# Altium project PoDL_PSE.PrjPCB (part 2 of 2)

## Sheet 03-LAN_3-Ports_Switch.SchDoc: LAN 3-Ports Switch
size A2; Date: Thu 9th Mar, 2023; CompanyName: RGT Supply and Service Ltd.; Engineer: Nattawut; Address1: 285/95 M.3 T.Tonpao Sankampaeng; Address2: Chiangmai 50130 Thailand Tel.+66 89 1645339; Revision: 1.6; SheetNumber: 3; SheetTotal: 4; ContentRev1: Original Document; dateREV1: 09-03-2023; NameRev1: Nattawut; NameRev3: Nattawut; NameRev2: Nattawut; NameRev4: Nattawut; NameRev5: Nattawut; NameRev6: Nattawut; dateREV2: 10-05-2023; dateREV3: 29-10-2023; dateREV4: 13-12-2023; dateREV5: 14-05-2024; dateREV6: 04-07-2024; ContentRev2: Change to AD controller; ContentRev3: Update Power Coupling; ContentRev4: Correct for IC4 unused ports; ContentRev5: Improve for EMC ability; ContentRev6: Add D36, Replace FB7 to R162; Rev1: 1.0; Rev2: 1.1; Rev3: 1.2; Rev4: 1.3; Rev5: 1.4; Rev6: 1.5; Project: PoDL; PageSetup: Record=PageOptions¦CenterHorizontal=True¦CenterVertical=True¦PrintScale=0.73¦XCorrection=1.00¦YCorrection=1.00¦PrintKind=0¦BorderSize=5000000¦LeftOffset=0¦BottomOffset=0¦Orientation=2¦PaperLength=1000¦PaperWidth=1000¦Scale=100¦PaperSource=7¦PrintQuality=-3¦MediaType=1¦DitherType=10¦PrintScaleMode=1¦PaperKind=A3¦PaperIndex=8; Rev7: 1.6; ContentRev7: Improve for EMC ability; dateREV7: 15-09-2024; NameRev7: Nattawut
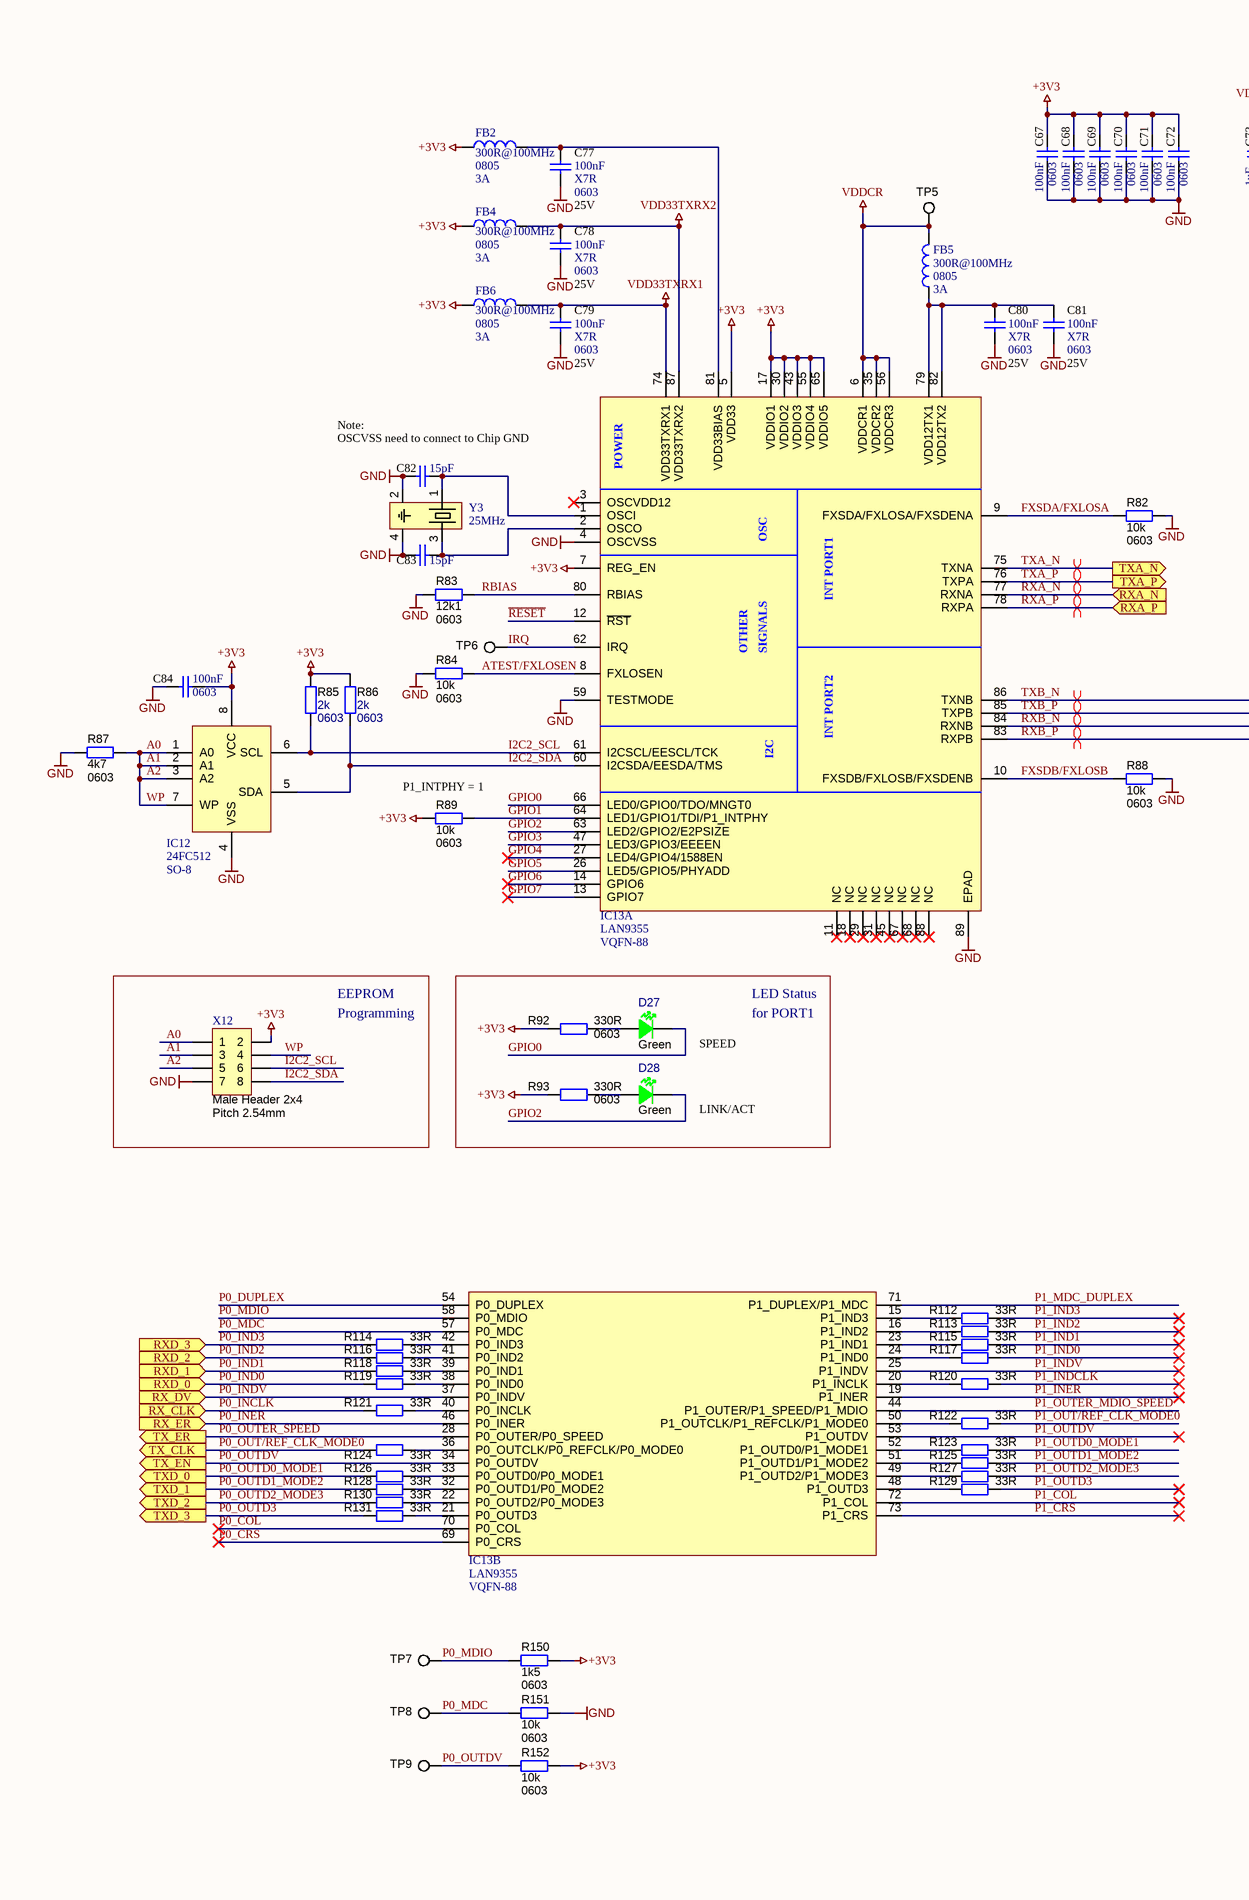
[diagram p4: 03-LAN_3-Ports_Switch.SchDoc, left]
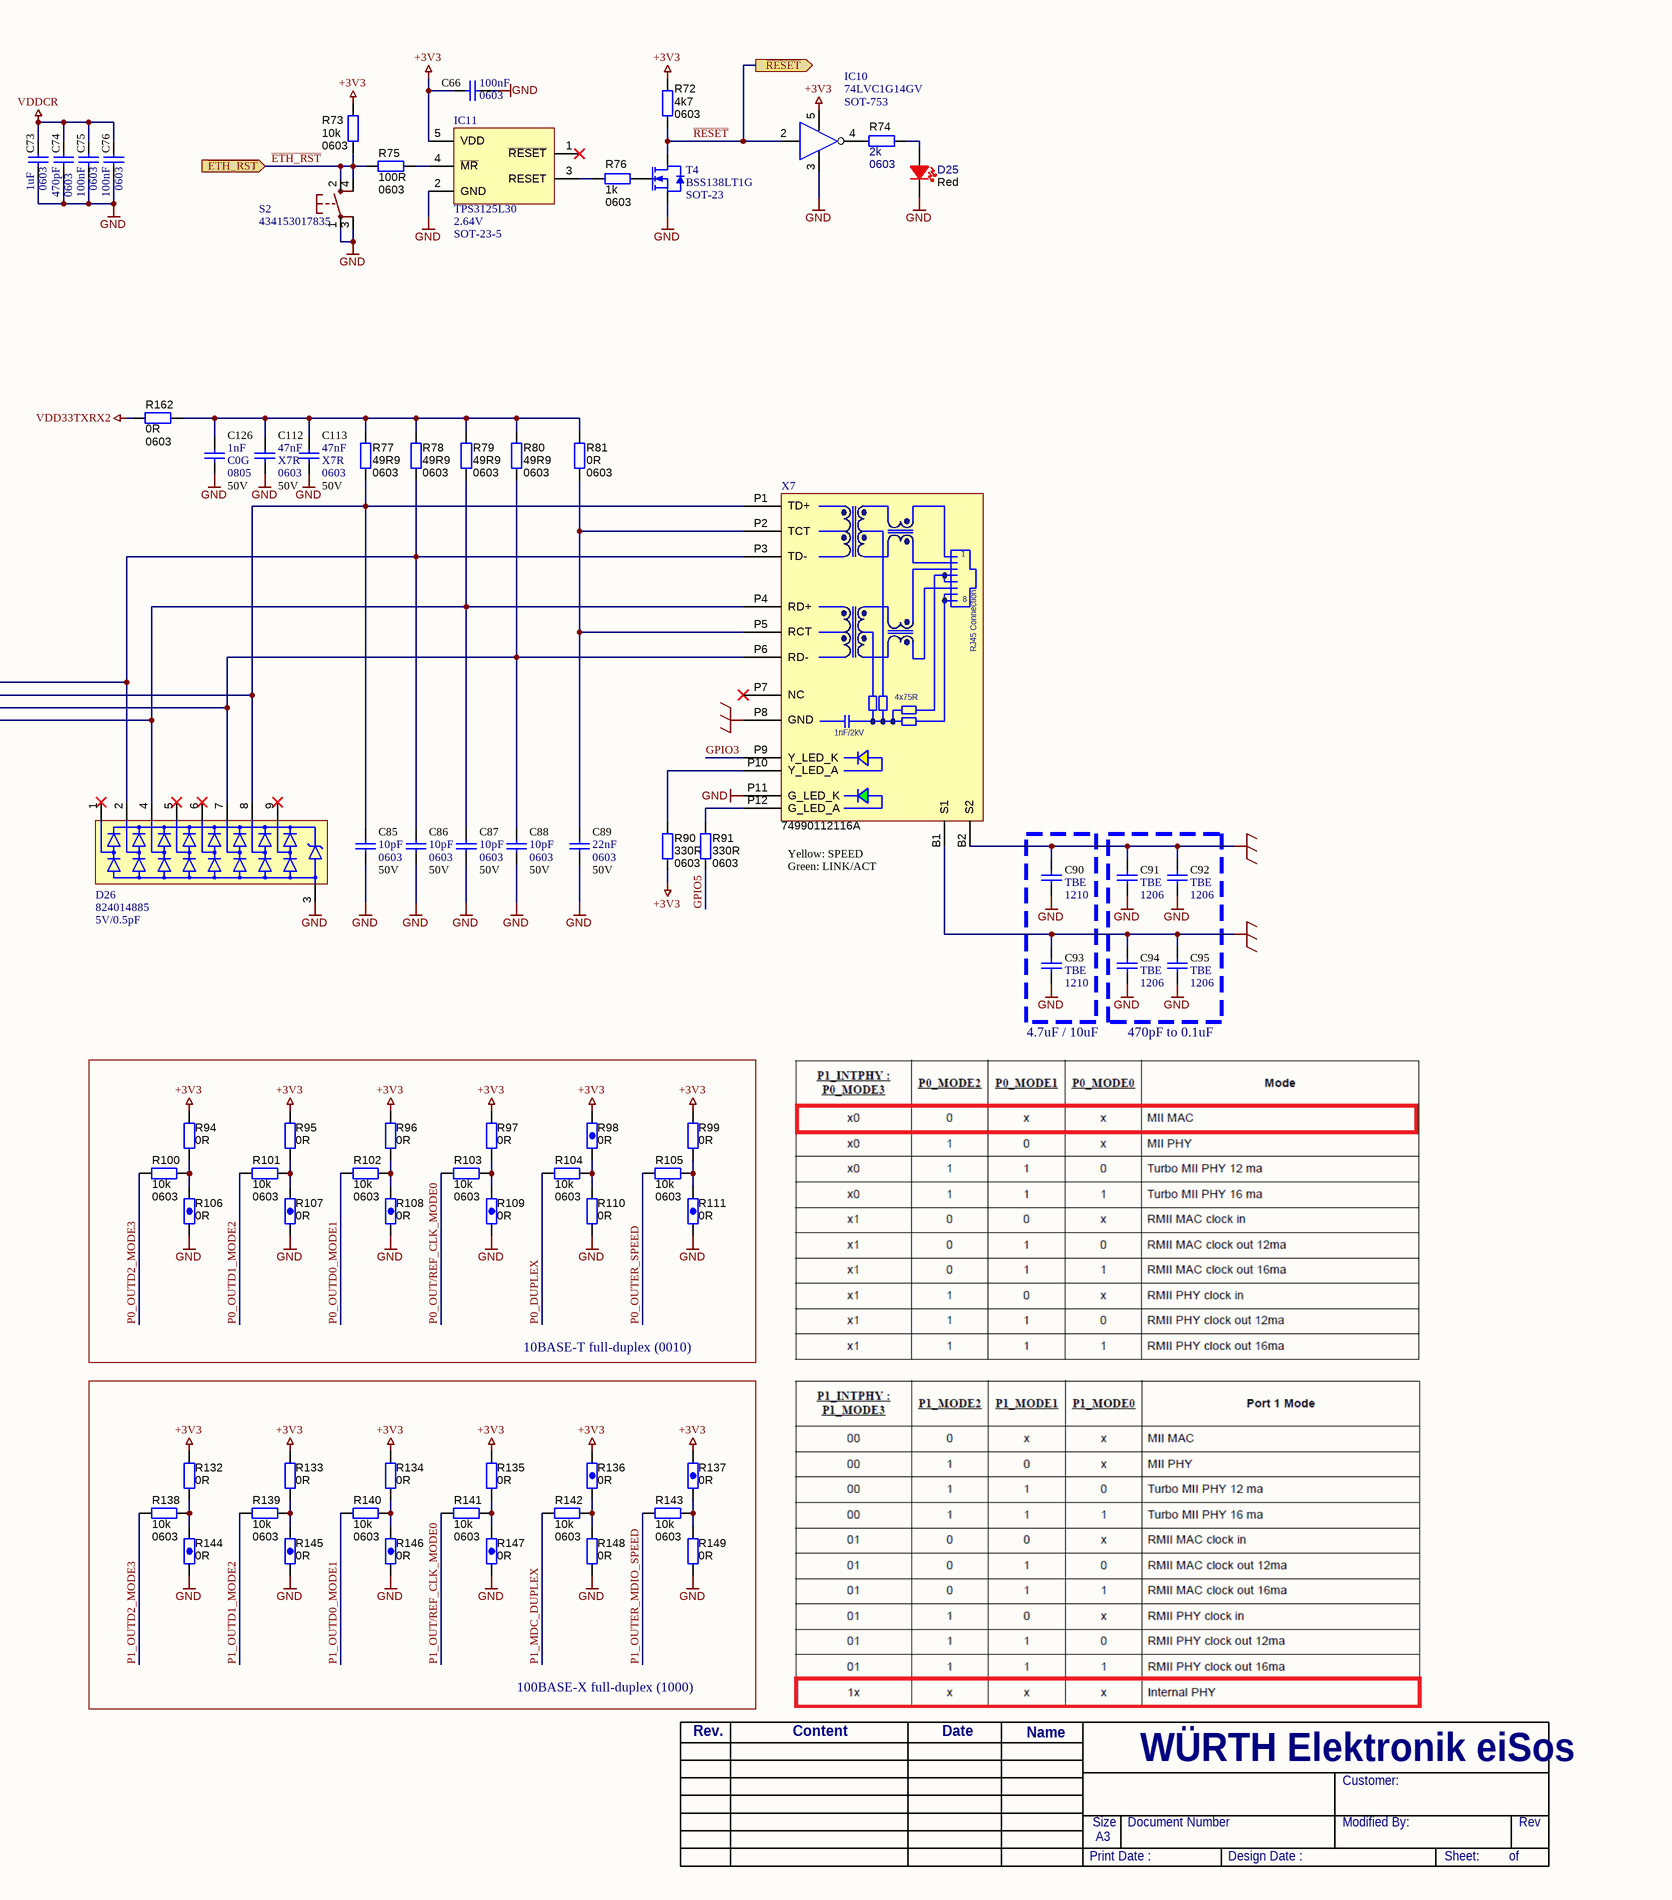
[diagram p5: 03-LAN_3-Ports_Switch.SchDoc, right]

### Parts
C66  value 100nF  PackageReference: 0603  [CC1608-0603]  (hidden comment: 885012206071)
C67  value 100nF  PackageReference: 0603  [CC1608-0603]  (hidden comment: 885012206071)
C68  value 100nF  PackageReference: 0603  [CC1608-0603]  (hidden comment: 885012206071)
C69  value 100nF  PackageReference: 0603  [CC1608-0603]  (hidden comment: 885012206071)
C70  value 100nF  PackageReference: 0603  [CC1608-0603]  (hidden comment: 885012206071)
C71  value 100nF  PackageReference: 0603  [CC1608-0603]  (hidden comment: 885012206071)
C72  value 100nF  PackageReference: 0603  [CC1608-0603]  (hidden comment: 885012206071)
C73  value 1uF  PackageReference: 0603  [CC1608-0603]  (hidden comment: 885012206026)
C74  value 470pF  PackageReference: 0603  [CC1608-0603]  (hidden comment: 885012206081)
C75  value 100nF  PackageReference: 0603  [CC1608-0603]  (hidden comment: 885012206071)
C76  value 100nF  PackageReference: 0603  [CC1608-0603]  (hidden comment: 885012206071)
C77  value 100nF  VDC_V: 25V  PackageReference: 0603  Dielectric: X7R  [CC1608-0603]  (hidden comment: 885012206071)
C78  value 100nF  VDC_V: 25V  PackageReference: 0603  Dielectric: X7R  [CC1608-0603]  (hidden comment: 885012206071)
C79  value 100nF  VDC_V: 25V  PackageReference: 0603  Dielectric: X7R  [CC1608-0603]  (hidden comment: 885012206071)
C80  value 100nF  VDC_V: 25V  PackageReference: 0603  Dielectric: X7R  [CC1608-0603]  (hidden comment: 885012206071)
C81  value 100nF  VDC_V: 25V  PackageReference: 0603  Dielectric: X7R  [CC1608-0603]  (hidden comment: 885012206071)
C82  value 15pF  [CC1005-0402]  (hidden comment: 885012005056)
C83  value 15pF  [CC1005-0402]  (hidden comment: 885012005056)
C84  value 100nF  PackageReference: 0603  [CC1608-0603]  (hidden comment: 885012206071)
C85  value 10pF  VDC_V: 50V  PackageReference: 0603  [CC1608-0603]  (hidden comment: 885012006051)
C86  value 10pF  VDC_V: 50V  PackageReference: 0603  [CC1608-0603]  (hidden comment: 885012006051)
C87  value 10pF  VDC_V: 50V  PackageReference: 0603  [CC1608-0603]  (hidden comment: 885012006051)
C88  value 10pF  VDC_V: 50V  PackageReference: 0603  [CC1608-0603]  (hidden comment: 885012006051)
C89  value 22nF  VDC_V: 50V  PackageReference: 0603  [CC1608-0603]  (hidden comment: 885012206091)
C90  value TBE  PackageReference: 1210  [CC3225-1210]
C91  value TBE  PackageReference: 1206  [CC3216-1206]
C92  value TBE  PackageReference: 1206  [CC3216-1206]
C93  value TBE  PackageReference: 1210  [CC3225-1210]
C94  value TBE  PackageReference: 1206  [CC3216-1206]
C95  value TBE  PackageReference: 1206  [CC3216-1206]
C112  value 47nF  VDC_V: 50V  PackageReference: 0603  Dielectric: X7R  [CC1608-0603]  (hidden comment: 885012206093)
C113  value 47nF  VDC_V: 50V  PackageReference: 0603  Dielectric: X7R  [CC1608-0603]  (hidden comment: 885012206093)
C126  value 1nF  VDC_V: 50V  PackageReference: 0805  Dielectric: C0G  [CC2012-0805]  (hidden comment: 885012007063)
D25  value Red  [LED1608 (0603) - Red]  (hidden comment: 150060SS75020)
D26  Voltage: 5V/0.5pF  [WE-TVS_824014885]  (hidden comment: 824014885)
D27  value Green  [LED1608 (0603) - Green]  (hidden comment: 150060VS75020)
D28  value Green  [LED1608 (0603) - Green]  (hidden comment: 150060VS75020)
FB2  value 300R@100MHz  PackageReference: 0805  I DC: 3A  [CF2012-0805]  (hidden comment: 742792031)
FB4  value 300R@100MHz  PackageReference: 0805  I DC: 3A  [CF2012-0805]  (hidden comment: 742792031)
FB5  value 300R@100MHz  PackageReference: 0805  I DC: 3A  [CF2012-0805]  (hidden comment: 742792031)
FB6  value 300R@100MHz  PackageReference: 0805  I DC: 3A  [CF2012-0805]  (hidden comment: 742792031)
IC10  value 74LVC1G14GV  PackageReference: SOT-753  [SOT-23-5]  (hidden comment: 74LVC1G14GV,125)
IC11  value TPS3125L30  Threshold Voltage: 2.64V  [SOT-23-5]  (hidden comment: TPS3125L30DBVR)
IC12  value 24FC512  [SO-8]  (hidden comment: 24FC512-I/SN)
IC13  value LAN9355  PackageReference: VQFN-88  [QFN-88 12X12MM]  (hidden comment: LAN9355I/ML)  (parts A,B of 2)
R72  value 4k7  PackageReference: 0603  [CR1608-0603]  (hidden comment: 560112116006)
R73  value 10k  PackageReference: 0603  [CR1608-0603]  (hidden comment: 560112116005)
R74  value 2k  PackageReference: 0603  [CR1608-0603]  (hidden comment: 560112116091)
R75  value 100R  PackageReference: 0603  [CR1608-0603]  (hidden comment: 560112116009)
R76  value 1k  PackageReference: 0603  [CR1608-0603]  (hidden comment: 560112116014)
R77  value 49R9  PackageReference: 0603  [CR1608-0603]  (hidden comment: 560112116133)
R78  value 49R9  PackageReference: 0603  [CR1608-0603]  (hidden comment: 560112116133)
R79  value 49R9  PackageReference: 0603  [CR1608-0603]  (hidden comment: 560112116133)
R80  value 49R9  PackageReference: 0603  [CR1608-0603]  (hidden comment: 560112116133)
R81  value 0R  PackageReference: 0603  [CR1608-0603]  (hidden comment: RC0603FR-070RL)
R82  value 10k  PackageReference: 0603  [CR1608-0603]  (hidden comment: 560112116005)
R83  value 12k1  PackageReference: 0603  [CR1608-0603]  (hidden comment: RC0603FR-0712K1L)
R84  value 10k  PackageReference: 0603  [CR1608-0603]  (hidden comment: 560112116005)
R85  value 2k  PackageReference: 0603  [CR1608-0603]  (hidden comment: 560112116091)
R86  value 2k  PackageReference: 0603  [CR1608-0603]  (hidden comment: 560112116091)
R87  value 4k7  PackageReference: 0603  [CR1608-0603]  (hidden comment: 560112116006)
R88  value 10k  PackageReference: 0603  [CR1608-0603]  (hidden comment: 560112116005)
R89  value 10k  PackageReference: 0603  [CR1608-0603]  (hidden comment: 560112116005)
R90  value 330R  PackageReference: 0603  [CR1608-0603]  (hidden comment: 560112116020)
R91  value 330R  PackageReference: 0603  [CR1608-0603]  (hidden comment: 560112116020)
R92  value 330R  PackageReference: 0603  [CR1608-0603]  (hidden comment: 560112116020)
R93  value 330R  PackageReference: 0603  [CR1608-0603]  (hidden comment: 560112116020)
R94  value 0R  [CR1608-0603]  (hidden comment: RC0603FR-070RL)
R95  value 0R  [CR1608-0603]  (hidden comment: RC0603FR-070RL)
R96  value 0R  [CR1608-0603]  (hidden comment: RC0603FR-070RL)
R97  value 0R  [CR1608-0603]  (hidden comment: RC0603FR-070RL)
R98  value 0R  [CR1608-0603]  (hidden comment: RC0603FR-070RL)
R99  value 0R  [CR1608-0603]  (hidden comment: RC0603FR-070RL)
R100  value 10k  PackageReference: 0603  [CR1608-0603]  (hidden comment: 560112116005)
R101  value 10k  PackageReference: 0603  [CR1608-0603]  (hidden comment: 560112116005)
R102  value 10k  PackageReference: 0603  [CR1608-0603]  (hidden comment: 560112116005)
R103  value 10k  PackageReference: 0603  [CR1608-0603]  (hidden comment: 560112116005)
R104  value 10k  PackageReference: 0603  [CR1608-0603]  (hidden comment: 560112116005)
R105  value 10k  PackageReference: 0603  [CR1608-0603]  (hidden comment: 560112116005)
R106  value 0R  [CR1608-0603]  (hidden comment: RC0603FR-070RL)
R107  value 0R  [CR1608-0603]  (hidden comment: RC0603FR-070RL)
R108  value 0R  [CR1608-0603]  (hidden comment: RC0603FR-070RL)
R109  value 0R  [CR1608-0603]  (hidden comment: RC0603FR-070RL)
R110  value 0R  [CR1608-0603]  (hidden comment: RC0603FR-070RL)
R111  value 0R  [CR1608-0603]  (hidden comment: RC0603FR-070RL)
R112  value 33R  [CR1608-0603]  (hidden comment: 560112116034)
R113  value 33R  [CR1608-0603]  (hidden comment: 560112116034)
R114  value 33R  [CR1608-0603]  (hidden comment: 560112116034)
R115  value 33R  [CR1608-0603]  (hidden comment: 560112116034)
R116  value 33R  [CR1608-0603]  (hidden comment: 560112116034)
R117  value 33R  [CR1608-0603]  (hidden comment: 560112116034)
R118  value 33R  [CR1608-0603]  (hidden comment: 560112116034)
R119  value 33R  [CR1608-0603]  (hidden comment: 560112116034)
R120  value 33R  [CR1608-0603]  (hidden comment: 560112116034)
R121  value 33R  [CR1608-0603]  (hidden comment: 560112116034)
R122  value 33R  [CR1608-0603]  (hidden comment: 560112116034)
R123  value 33R  [CR1608-0603]  (hidden comment: 560112116034)
R124  value 33R  [CR1608-0603]  (hidden comment: 560112116034)
R125  value 33R  [CR1608-0603]  (hidden comment: 560112116034)
R126  value 33R  [CR1608-0603]  (hidden comment: 560112116034)
R127  value 33R  [CR1608-0603]  (hidden comment: 560112116034)
R128  value 33R  [CR1608-0603]  (hidden comment: 560112116034)
R129  value 33R  [CR1608-0603]  (hidden comment: 560112116034)
R130  value 33R  [CR1608-0603]  (hidden comment: 560112116034)
R131  value 33R  [CR1608-0603]  (hidden comment: 560112116034)
R132  value 0R  [CR1608-0603]  (hidden comment: RC0603FR-070RL)
R133  value 0R  [CR1608-0603]  (hidden comment: RC0603FR-070RL)
R134  value 0R  [CR1608-0603]  (hidden comment: RC0603FR-070RL)
R135  value 0R  [CR1608-0603]  (hidden comment: RC0603FR-070RL)
R136  value 0R  [CR1608-0603]  (hidden comment: RC0603FR-070RL)
R137  value 0R  [CR1608-0603]  (hidden comment: RC0603FR-070RL)
R138  value 10k  PackageReference: 0603  [CR1608-0603]  (hidden comment: 560112116005)
R139  value 10k  PackageReference: 0603  [CR1608-0603]  (hidden comment: 560112116005)
R140  value 10k  PackageReference: 0603  [CR1608-0603]  (hidden comment: 560112116005)
R141  value 10k  PackageReference: 0603  [CR1608-0603]  (hidden comment: 560112116005)
R142  value 10k  PackageReference: 0603  [CR1608-0603]  (hidden comment: 560112116005)
R143  value 10k  PackageReference: 0603  [CR1608-0603]  (hidden comment: 560112116005)
R144  value 0R  [CR1608-0603]  (hidden comment: RC0603FR-070RL)
R145  value 0R  [CR1608-0603]  (hidden comment: RC0603FR-070RL)
R146  value 0R  [CR1608-0603]  (hidden comment: RC0603FR-070RL)
R147  value 0R  [CR1608-0603]  (hidden comment: RC0603FR-070RL)
R148  value 0R  [CR1608-0603]  (hidden comment: RC0603FR-070RL)
R149  value 0R  [CR1608-0603]  (hidden comment: RC0603FR-070RL)
R150  value 1k5  PackageReference: 0603  [CR1608-0603]  (hidden comment: 560112116038)
R151  value 10k  PackageReference: 0603  [CR1608-0603]  (hidden comment: 560112116005)
R152  value 10k  PackageReference: 0603  [CR1608-0603]  (hidden comment: 560112116005)
R162  value 0R  PackageReference: 0603  [CR1608-0603]  (hidden comment: RC0603FR-070RL)
S2  434153017835  [434153017835]
T4  BSS138LT1G  [SOT-23]
TP5  (no value)  [TESTPOINT 1.5mm]
TP6  (no value)  [TESTPOINT 1.5mm]
TP7  (no value)  [TESTPOINT 1.5mm]
TP8  (no value)  [TESTPOINT 1.5mm]
TP9  (no value)  [TESTPOINT 1.5mm]
X7  74990112116A  [RJ45_74990112116A]
X12  value Male Header 2x4  PackageReference: Pitch 2.54mm  [HDR2X4]  (hidden comment: 61300821121)
Y3  value 25MHz  [CRYSTAL_3225]  (hidden comment: 830055299)

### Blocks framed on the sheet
10BASE-T full-duplex (0010): R94-R111
100BASE-X full-duplex (1000): R132-R149

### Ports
RX_CLK (in), RX_DV (in), RX_ER (in), RXA_N (in), RXA_P (in), RXD_0 (in), RXD_1 (in), RXD_2 (in), RXD_3 (in), TX_CLK (out), TX_EN (out), TX_ER (out), TXA_N (out), TXA_P (out), TXD_0 (out), TXD_1 (out), TXD_2 (out), TXD_3 (out), ~{ETH_RST} (in), ~{RESET} (out)

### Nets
+3V3: C66.2 C67.1 C68.1 C69.1 C70.1 C71.1 C72.1 C84.2 FB2.1 FB4.1 FB6.1 IC10.5(Vcc) IC11.5(VDD) IC12.8(VCC) IC13.5(VDD33) IC13.7(REG_EN) IC13.17(VDDIO1) IC13.30(VDDIO2) IC13.43(VDDIO3) IC13.55(VDDIO4) IC13.65(VDDIO5) R72.1 R73.2 R85.1 R86.1 R89.1 R90.2 R92.1 R93.1 R94.2 R95.2 R96.2 R97.2 R98.2 R99.2 R132.2 R133.2 R134.2 R135.2 R136.2 R137.2 R150.2 R152.1 X12.2
GND: C66.1 C67.2 C68.2 C69.2 C70.2 C71.2 C72.2 C73.1 C74.2 C75.2 C76.2 C77.2 C78.2 C79.2 C80.2 C81.2 C82.1 C83.1 C84.1 C85.2 C86.2 C87.2 C88.2 C89.2 C90.2 C91.2 C92.2 C93.2 C94.2 C95.2 C112.2 C113.2 C126.2 D25.1 D26.3(GND) IC10.3(Gnd) IC11.2(GND) IC12.4(VSS) IC13.4(OSCVSS) IC13.59(TESTMODE) IC13.89(EPAD) R82.2 R83.2 R84.1 R87.2 R88.2 R106.1 R107.1 R108.1 R109.1 R110.1 R111.1 R144.1 R145.1 R146.1 R147.1 R148.1 R149.1 R151.1 S2.1 S2.3 T4.2(S) X7.P11(G_LED_K) X12.7 Y3.2 Y3.4
SHIELD: C90.1 C91.1 C92.1 C93.1 C94.1 C95.1 X7.B1(S1) X7.B2(S2) X7.P8(GND)
VDD33TXRX1: C79.1 FB6.2 IC13.74(VDD33TXRX1)
VDD33TXRX2: C78.1 FB4.2 IC13.87(VDD33TXRX2) R162.1
VDDCR: C73.2 C74.1 C75.1 C76.1 FB5.2 IC13.6(VDDCR1) IC13.35(VDDCR2) IC13.56(VDDCR3) TP5.1
A0: IC12.1(A0) IC12.2(A1) IC12.3(A2) IC12.7(WP) R87.1 X12.1 X12.3 X12.4 X12.5  [also labelled A1, A2, WP]
ATEST/FXLOSEN: IC13.8(FXLOSEN) R84.2
~{ETH_RST}: R73.1 R75.1 S2.2 S2.4 ; port ~{ETH_RST}
FXSDA/FXLOSA: IC13.9(FXSDA/FXLOSA/FXSDENA) R82.1
FXSDB/FXLOSB: IC13.10(FXSDB/FXLOSB/FXSDENB) R88.1
GPIO0: D27.1 IC13.66(LED0/GPIO0/TDO/MNGT0)
GPIO1: IC13.64(LED1/GPIO1/TDI/P1_INTPHY) R89.2
GPIO2: D28.1 IC13.63(LED2/GPIO2/E2PSIZE)
GPIO3: IC13.47(LED3/GPIO3/EEEEN) X7.P9(Y_LED_K)
GPIO4: IC13.27(LED4/GPIO4/1588EN)
GPIO5: IC13.26(LED5/GPIO5/PHYADD) R91.2
GPIO6: IC13.14(GPIO6)
GPIO7: IC13.13(GPIO7)
I2C2_SCL: IC12.6(SCL) IC13.61(I2CSCL/EESCL/TCK) R85.2 X12.6
I2C2_SDA: IC12.5(SDA) IC13.60(I2CSDA/EESDA/TMS) R86.2 X12.8
IRQ: IC13.62(IRQ) TP6.1
P0_COL: IC13.70(P0_COL)
P0_CRS: IC13.69(P0_CRS)
P0_DUPLEX: IC13.54(P0_DUPLEX) R104.1
P0_INCLK: R121.1 ; port RX_CLK
P0_IND0: R119.1 ; port RXD_0
P0_IND1: R118.1 ; port RXD_1
P0_IND2: R116.1 ; port RXD_2
P0_IND3: R114.1 ; port RXD_3
P0_INDV: IC13.37(P0_INDV) ; port RX_DV
P0_INER: IC13.46(P0_INER) ; port RX_ER
P0_MDC: IC13.57(P0_MDC) R151.2 TP8.1
P0_MDIO: IC13.58(P0_MDIO) R150.1 TP7.1
P0_OUT/REF_CLK_MODE0: R103.1 R124.1 ; port TX_CLK
P0_OUTD0_MODE1: R102.1 R126.1 ; port TXD_0
P0_OUTD1_MODE2: R101.1 R128.1 ; port TXD_1
P0_OUTD2_MODE3: R100.1 R130.1 ; port TXD_2
P0_OUTD3: R131.1 ; port TXD_3
P0_OUTDV: IC13.34(P0_OUTDV) R152.2 TP9.1 ; port TX_EN
P0_OUTER_SPEED: IC13.28(P0_OUTER/P0_SPEED) R105.1 ; port TX_ER
P1_COL: IC13.72(P1_COL)
P1_CRS: IC13.73(P1_CRS)
P1_IND0: R117.2
P1_IND1: R115.2
P1_IND2: R113.2
P1_IND3: R112.2
P1_INDCLK: R120.2
P1_INDV: IC13.25(P1_INDV)
P1_INER: IC13.19(P1_INER)
P1_MDC_DUPLEX: IC13.71(P1_DUPLEX/P1_MDC) R142.1
P1_OUT/REF_CLK_MODE0: R122.2 R141.1
P1_OUTD0_MODE1: R123.2 R140.1
P1_OUTD1_MODE2: R125.2 R139.1
P1_OUTD2_MODE3: R127.2 R138.1
P1_OUTD3: R129.2
P1_OUTDV: IC13.53(P1_OUTDV)
P1_OUTER_MDIO_SPEED: IC13.44(P1_OUTER/P1_SPEED/P1_MDIO) R143.1
~{RESET}: IC10.2(A) IC13.12(~{RST}) R72.2 T4.3(D) ; port ~{RESET}
RBIAS: IC13.80(RBIAS) R83.1
RXA_N: IC13.77(RXNA) ; port RXA_N
RXA_P: IC13.78(RXPA) ; port RXA_P
RXB_N: C88.1 D26.7(IO6) IC13.84(RXNB) R80.1 X7.P6(RD-)
RXB_P: C87.1 D26.4(IO3) IC13.83(RXPB) R79.1 X7.P4(RD+)
TXA_N: IC13.75(TXNA) ; port TXA_N
TXA_P: IC13.76(TXPA) ; port TXA_P
TXB_N: C86.1 D26.2(IO2) IC13.86(TXNB) R78.1 X7.P3(TD-)
TXB_P: C85.1 D26.8(IO7) IC13.85(TXPB) R77.1 X7.P1(TD+)
NetC77_1: C77.1 FB2.2 IC13.81(VDD33BIAS)
NetC80_1: C80.1 C81.1 FB5.1 IC13.79(VDD12TX1) IC13.82(VDD12TX2)
NetC82_2: C82.2 IC13.1(OSCI) Y3.1
NetC83_2: C83.2 IC13.2(OSCO) Y3.3
NetC89_1: C89.1 R81.1 X7.P2(TCT) X7.P5(RCT)
NetC112_1: C112.1 C113.1 C126.1 R77.2 R78.2 R79.2 R80.2 R81.2 R162.2
NetD25_2: D25.2 R74.2
NetD27_2: D27.2 R92.2
NetD28_2: D28.2 R93.2
NetIC10_4: IC10.4(Y) R74.1
NetIC11_3: IC11.3(RESET) R76.1
NetIC11_4: IC11.4(~{MR}) R75.2
NetIC13_15: IC13.15(P1_IND3) R112.1
NetIC13_16: IC13.16(P1_IND2) R113.1
NetIC13_20: IC13.20(P1_INCLK) R120.1
NetIC13_21: IC13.21(P0_OUTD3) R131.2
NetIC13_22: IC13.22(P0_OUTD2/P0_MODE3) R130.2
NetIC13_23: IC13.23(P1_IND1) R115.1
NetIC13_24: IC13.24(P1_IND0) R117.1
NetIC13_32: IC13.32(P0_OUTD1/P0_MODE2) R128.2
NetIC13_33: IC13.33(P0_OUTD0/P0_MODE1) R126.2
NetIC13_36: IC13.36(P0_OUTCLK/P0_REFCLK/P0_MODE0) R124.2
NetIC13_38: IC13.38(P0_IND0) R119.2
NetIC13_39: IC13.39(P0_IND1) R118.2
NetIC13_40: IC13.40(P0_INCLK) R121.2
NetIC13_41: IC13.41(P0_IND2) R116.2
NetIC13_42: IC13.42(P0_IND3) R114.2
NetIC13_48: IC13.48(P1_OUTD3) R129.1
NetIC13_49: IC13.49(P1_OUTD2/P1_MODE3) R127.1
NetIC13_50: IC13.50(P1_OUTCLK/P1_REFCLK/P1_MODE0) R122.1
NetIC13_51: IC13.51(P1_OUTD1/P1_MODE2) R125.1
NetIC13_52: IC13.52(P1_OUTD0/P1_MODE1) R123.1
NetR76_2: R76.2 T4.1(G)
NetR90_1: R90.1 X7.P10(Y_LED_A)
NetR91_1: R91.1 X7.P12(G_LED_A)
NetR94_1: R94.1 R100.2 R106.2
NetR95_1: R95.1 R101.2 R107.2
NetR96_1: R96.1 R102.2 R108.2
NetR97_1: R97.1 R103.2 R109.2
NetR98_1: R98.1 R104.2 R110.2
NetR99_1: R99.1 R105.2 R111.2
NetR132_1: R132.1 R138.2 R144.2
NetR133_1: R133.1 R139.2 R145.2
NetR134_1: R134.1 R140.2 R146.2
NetR135_1: R135.1 R141.2 R147.2
NetR136_1: R136.1 R142.2 R148.2
NetR137_1: R137.1 R143.2 R149.2

Not connected (* = marked no-connect by the designer): D26 1(IO1)* 5(IO4)* 6(IO5)* 9(IO8)*; IC11 1(~{RESET})*; IC13 3(OSCVDD12)* 11(NC)* 18(NC)* 29(NC)* 31(NC)* 45(NC)* 67(NC)* 68(NC)* 88(NC)*; X7 P7(NC)*

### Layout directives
differential pair: RXA_N, RXA_P, RXB_N, RXB_P, TXA_N, TXA_P, TXB_N, TXB_P

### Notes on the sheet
- (near C82) Note:
  OSCVSS need to connect to Chip GND
- (near R89) P1_INTPHY = 1
- (near X7) Yellow: SPEED
  Green: LINK/ACT
- EEPROM
- LED Status
- Programming
- SPEED
- for PORT1
- 4.7uF / 10uF
- 470pF to 0.1uF
- (near D28) LINK/ACT
- Rev.
- Content
- Date
- Name
- WÜRTH Elektronik eiSos
- Customer:
- Print Date :
- Size
- A3
- Document Number
- Design Date :
- Modified By:
- Sheet:
- of
- Rev

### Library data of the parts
C66-C72 C75-C81 C84 = 885012206071: CAP, CERM, 100nF, 25V, +/-10%, X7R, 0603; Manufacturer: Wurth; Polarized: N; TaMax_C: 125; TaMin_C: -55; Tolerance_%: 10; CompType: Capacitor
C73 = 885012206026: CAP, CERM, 1uF, 10V, +/-10%, X7R, 0603; Manufacturer: Wurth; Polarized: N; TaMax_C: 125; TaMin_C: -55; Tolerance_%: 10%; CompType: Capacitor
C74 = 885012206081: CAP, CERM, 470pF, 50V, +/-10%, X7R, 0603; Manufacturer: Wurth; Polarized: N; TaMax_C: 125; TaMin_C: -55; Tolerance_%: 10; CompType: Capacitor
C82 C83 = 885012005056: CAP, CERM, 15pF, 50V, +/-5%, C0G, 0402; Manufacturer: Wurth; Polarized: N; TaMax_C: 125; TaMin_C: -55; Tolerance_%: 5; CompType: Capacitor
C85-C88 = 885012006051: CAP, CERM, 10pF, 50V, +/-5%, C0G, 0603; Manufacturer: Wurth; Polarized: N; TaMax_C: 125; TaMin_C: -55; Tolerance_%: 5; CompType: Capacitor
C89 = 885012206091: CAP, CERM, 22nF, 50V, +/-10%, X7R, 0603; Manufacturer: Wurth; Polarized: N; TaMax_C: 125; TaMin_C: -55; Tolerance_%: 10%; CompType: Capacitor
C90 C93 = TBE_CAP_1210: CAP, CERM, TBE, 1210; Polarized: N; TaMax_C: 125; TaMin_C: -55; CompType: Capacitor
C91 C92 C94 C95 = TBE_CAP_1206: CAP, CERM, TBE, 1206; Polarized: N; TaMax_C: 125; TaMin_C: -55; CompType: Capacitor
C112 C113 = 885012206093: CAP, CERM, 47nF, 50V, +/-10%, X7R, 0603; Manufacturer: Wurth; Polarized: N; TaMax_C: 125; TaMin_C: -55; Tolerance_%: 10%; CompType: Capacitor
C126 = 885012007063: CAP, CERM, 1nF, 50V, +/-5%, C0G, 0805; Manufacturer: Wurth; Polarized: N; TaMax_C: 125; TaMin_C: -55; Tolerance_%: 5; CompType: Capacitor
D25 = 150060SS75020: LED 645NM RED 0603 SMD; Manufacturer: Wurth
D26 = 824014885: DIODE, TVS Super Speed , 5V, 8CH, 3.8x1.0mm; Manufacturer: Wurth
D27 D28 = 150060VS75020: LED 572NM GREEN 0603 SMD; Manufacturer: Wurth
FB2 FB4-FB6 = 742792031: Ferrite Bead 300R @ 100MHz / 0805 / 3.0A; Manufacturer: Wurth
IC10 = 74LVC1G14GV,125_2: IC SCHMITT INVERTER, 1.65-5.5V, 1CH, SOT-753; Manufacturer: Nexperia
IC11 = TPS3125L30DBVR: IC Supervisory, 0.75-3.3V, SOT-23-5; Manufacturer: TI
IC12 = 24FC512-I/SN: IC EEPROM, I2C, 512kb, 1MHz, 1.7-5.5V, SO-8; Manufacturer: Microchip
IC13 = LAN9355I/ML: IC ETHERNET SWITCH 3PORT, VQFN-88; Manufacturer: Microchip
R72 R87 = 560112116006: RES, 4.7kohm, 1%, 0.1W, 0603; Manufacturer: Wurth; CompType: Resistor; Power_W: 0.1
R73 R82 R84 R88 R89 R100-R105 R138-R143 R151 R152 = 560112116005: RES, 10kohm, 1%, 0.1W, 0603; Manufacturer: Wurth; CompType: Resistor; Power_W: 0.1
R74 R85 R86 = 560112116091: RES, 2kohm, 1%, 0.1W, 0603; Manufacturer: Wurth; CompType: Resistor; Power_W: 0.1
R75 = 560112116009: RES, 100 ohm, 1%, 0.1W, 0603; Manufacturer: Wurth; CompType: Resistor; Power_W: 0.1
R76 = 560112116014: RES, 1kohm, 1%, 0.1W, 0603; Manufacturer: Wurth; CompType: Resistor; Power_W: 0.1
R77-R80 = 560112116133: RES, 49.9 ohm, 1%, 0.1W, 0603; Manufacturer: Wurth; CompType: Resistor; Power_W: 0.1
R81 R94-R99 R106-R111 R132-R137 R144-R149 R162 = RC0603FR-070RL: RES, 0 ohm, 1%, 0.1W, 0603; Manufacturer: Yageo; CompType: Resistor; Power_W: 0.1
R83 = RC0603FR-0712K1L: RES, 12.1kohm, 1%, 0.1W, 0603; Manufacturer: Yageo; CompType: Resistor; Power_W: 0.1
R90-R93 = 560112116020: RES, 330 ohm, 1%, 0.1W, 0603; Manufacturer: Wurth; CompType: Resistor; Power_W: 0.1
R112-R131 = 560112116034: RES, 33 ohm, 1%, 0.1W, 0603; Manufacturer: Wurth; CompType: Resistor; Power_W: 0.1
R150 = 560112116038: RES, 1.5kohm, 1%, 0.1W, 0603; Manufacturer: Wurth; CompType: Resistor; Power_W: 0.1
S2 = 434153017835: SWITCH TACTILE, SPST-NO, 350gf, 0.05A, 12V; Manufacturer: Wurth
T4 = BSS138LT1G: MOSFET, N-CH, 50V, 0.2A, SOT-23; Manufacturer: Onsemi
TP5-TP9 = TP / 1.5mm: Test Point, SMT, Miniature; Value: 1.5mm
X7 = 74990112116A: CON, Ethernet, Int Magnetics, 8P+LED, 1x1 Tab-UP, INS; Manufacturer: Wurth; CompType: Connector
X12 = 61300821121: CON, Header, Male, 2x4P, P2.54mm, Straight, INS; Manufacturer: Wurth; CompType: Connector
Y3 = 830055299: Crystal / 25MHz / 18pF / 30ppm; Manufacturer: Wurth

## Sheet 04-LAN_to_USB-C.SchDoc: LAN to USB-C
size A2; Date: Thu 9th Mar, 2023; CompanyName: RGT Supply and Service Ltd.; Engineer: Nattawut; Address1: 285/95 M.3 T.Tonpao Sankampaeng; Address2: Chiangmai 50130 Thailand Tel.+66 89 1645339; Revision: 1.6; SheetNumber: 4; SheetTotal: 4; ContentRev1: Original Document; dateREV1: 09-03-2023; NameRev1: Nattawut; NameRev3: Nattawut; NameRev2: Nattawut; NameRev4: Nattawut; NameRev5: Nattawut; NameRev6: Nattawut; dateREV2: 10-05-2023; dateREV3: 29-10-2023; dateREV4: 13-12-2023; dateREV5: 14-05-2024; dateREV6: 04-07-2024; ContentRev2: Change to AD controller; ContentRev3: Update Power Coupling; ContentRev4: Correct for IC4 unused ports; ContentRev5: Improve for EMC ability; ContentRev6: Add D36, Replace FB7 to R162; Rev1: 1.0; Rev2: 1.1; Rev3: 1.2; Rev4: 1.3; Rev5: 1.4; Rev6: 1.5; Project: PoDL; PageSetup: Record=PageOptions¦CenterHorizontal=True¦CenterVertical=True¦PrintScale=0.73¦XCorrection=1.00¦YCorrection=1.00¦PrintKind=0¦BorderSize=5000000¦LeftOffset=0¦BottomOffset=0¦Orientation=2¦PaperLength=1000¦PaperWidth=1000¦Scale=100¦PaperSource=7¦PrintQuality=-3¦MediaType=1¦DitherType=10¦PrintScaleMode=1¦PaperKind=A3¦PaperIndex=8; Rev7: 1.6; ContentRev7: Improve for EMC ability; dateREV7: 15-09-2024; NameRev7: Nattawut
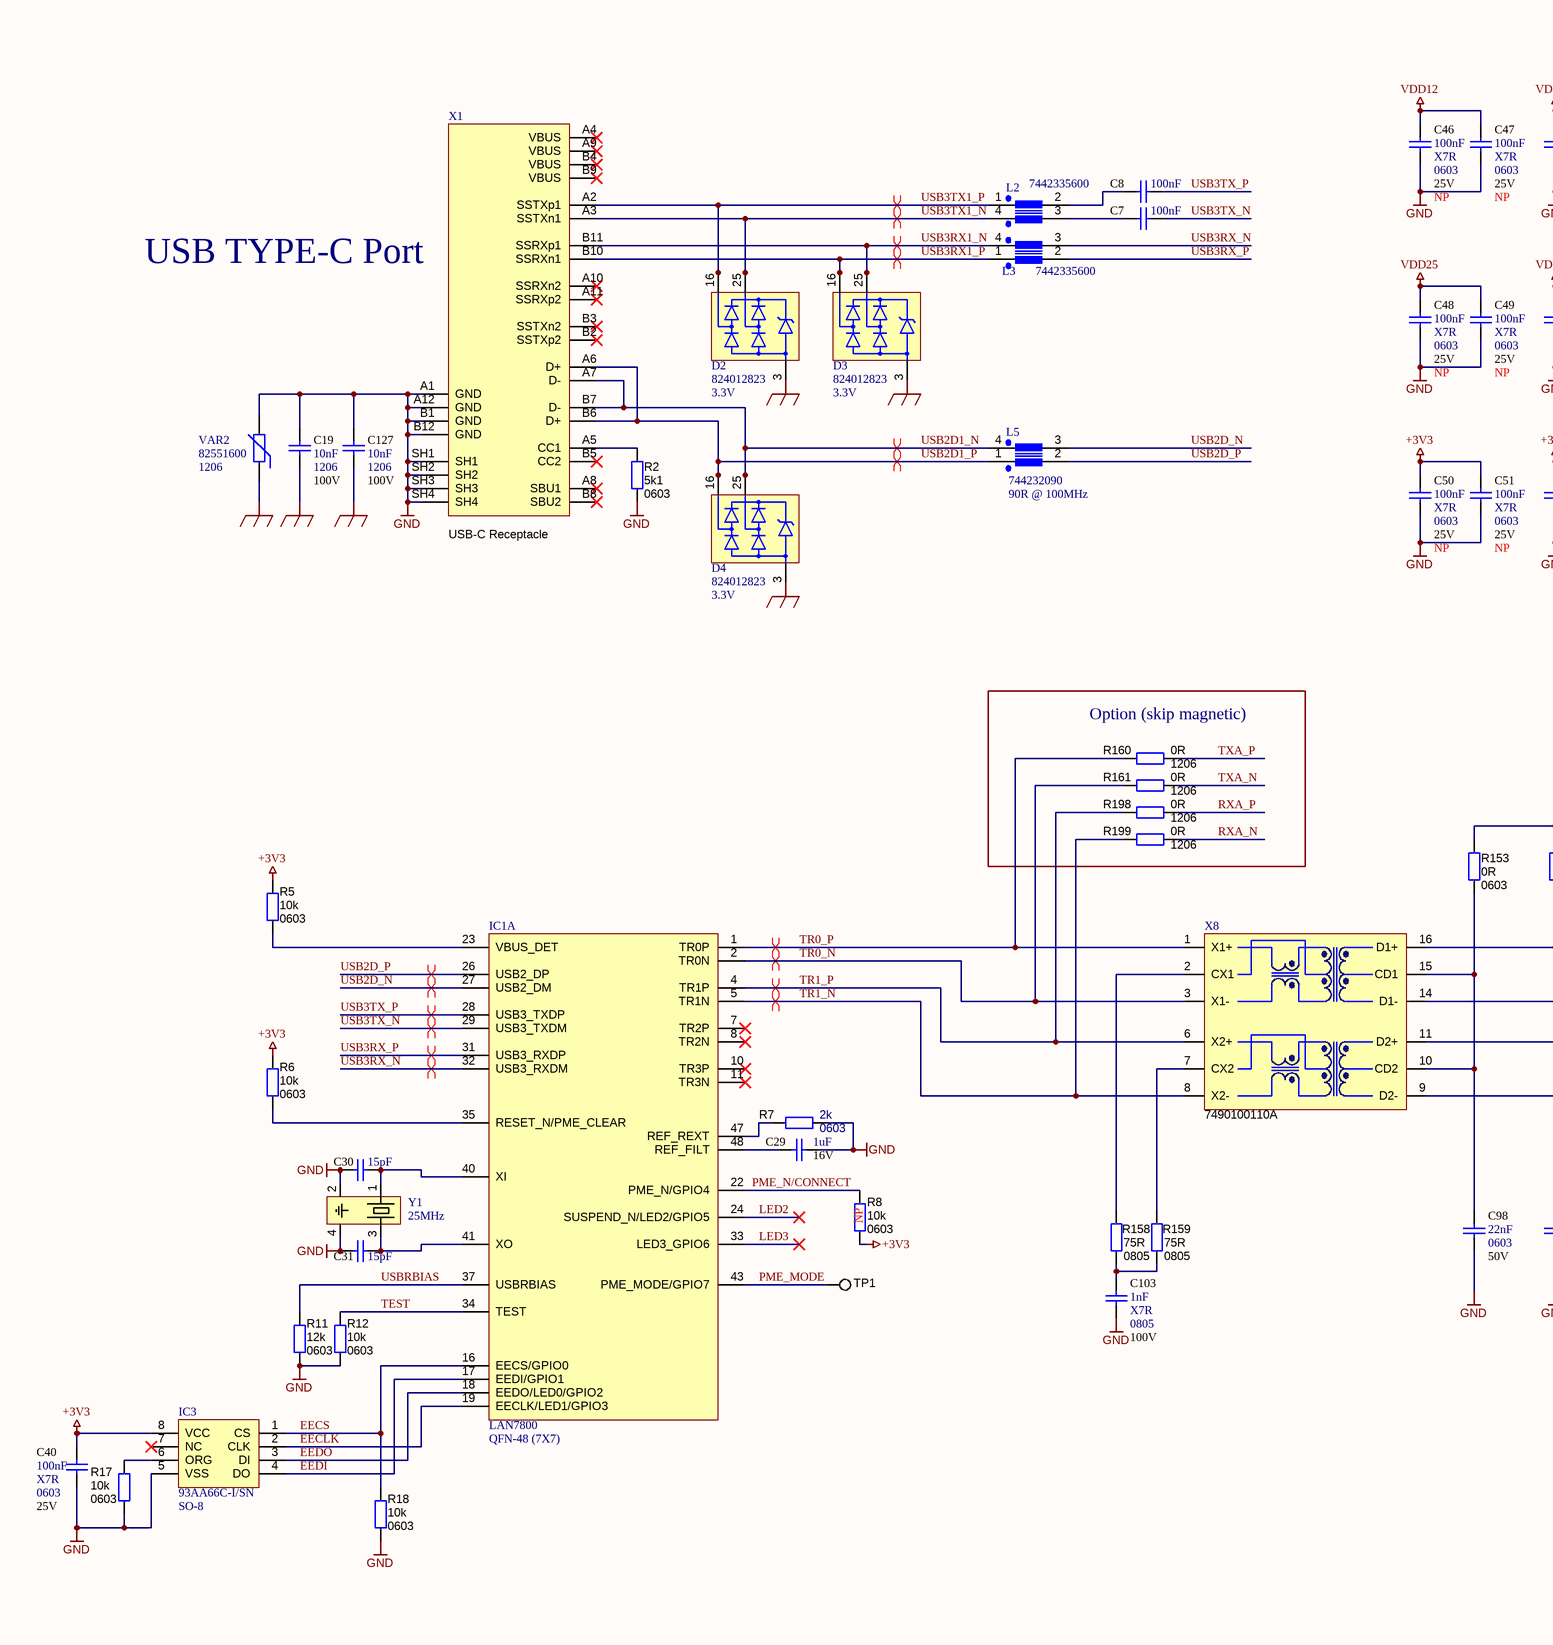
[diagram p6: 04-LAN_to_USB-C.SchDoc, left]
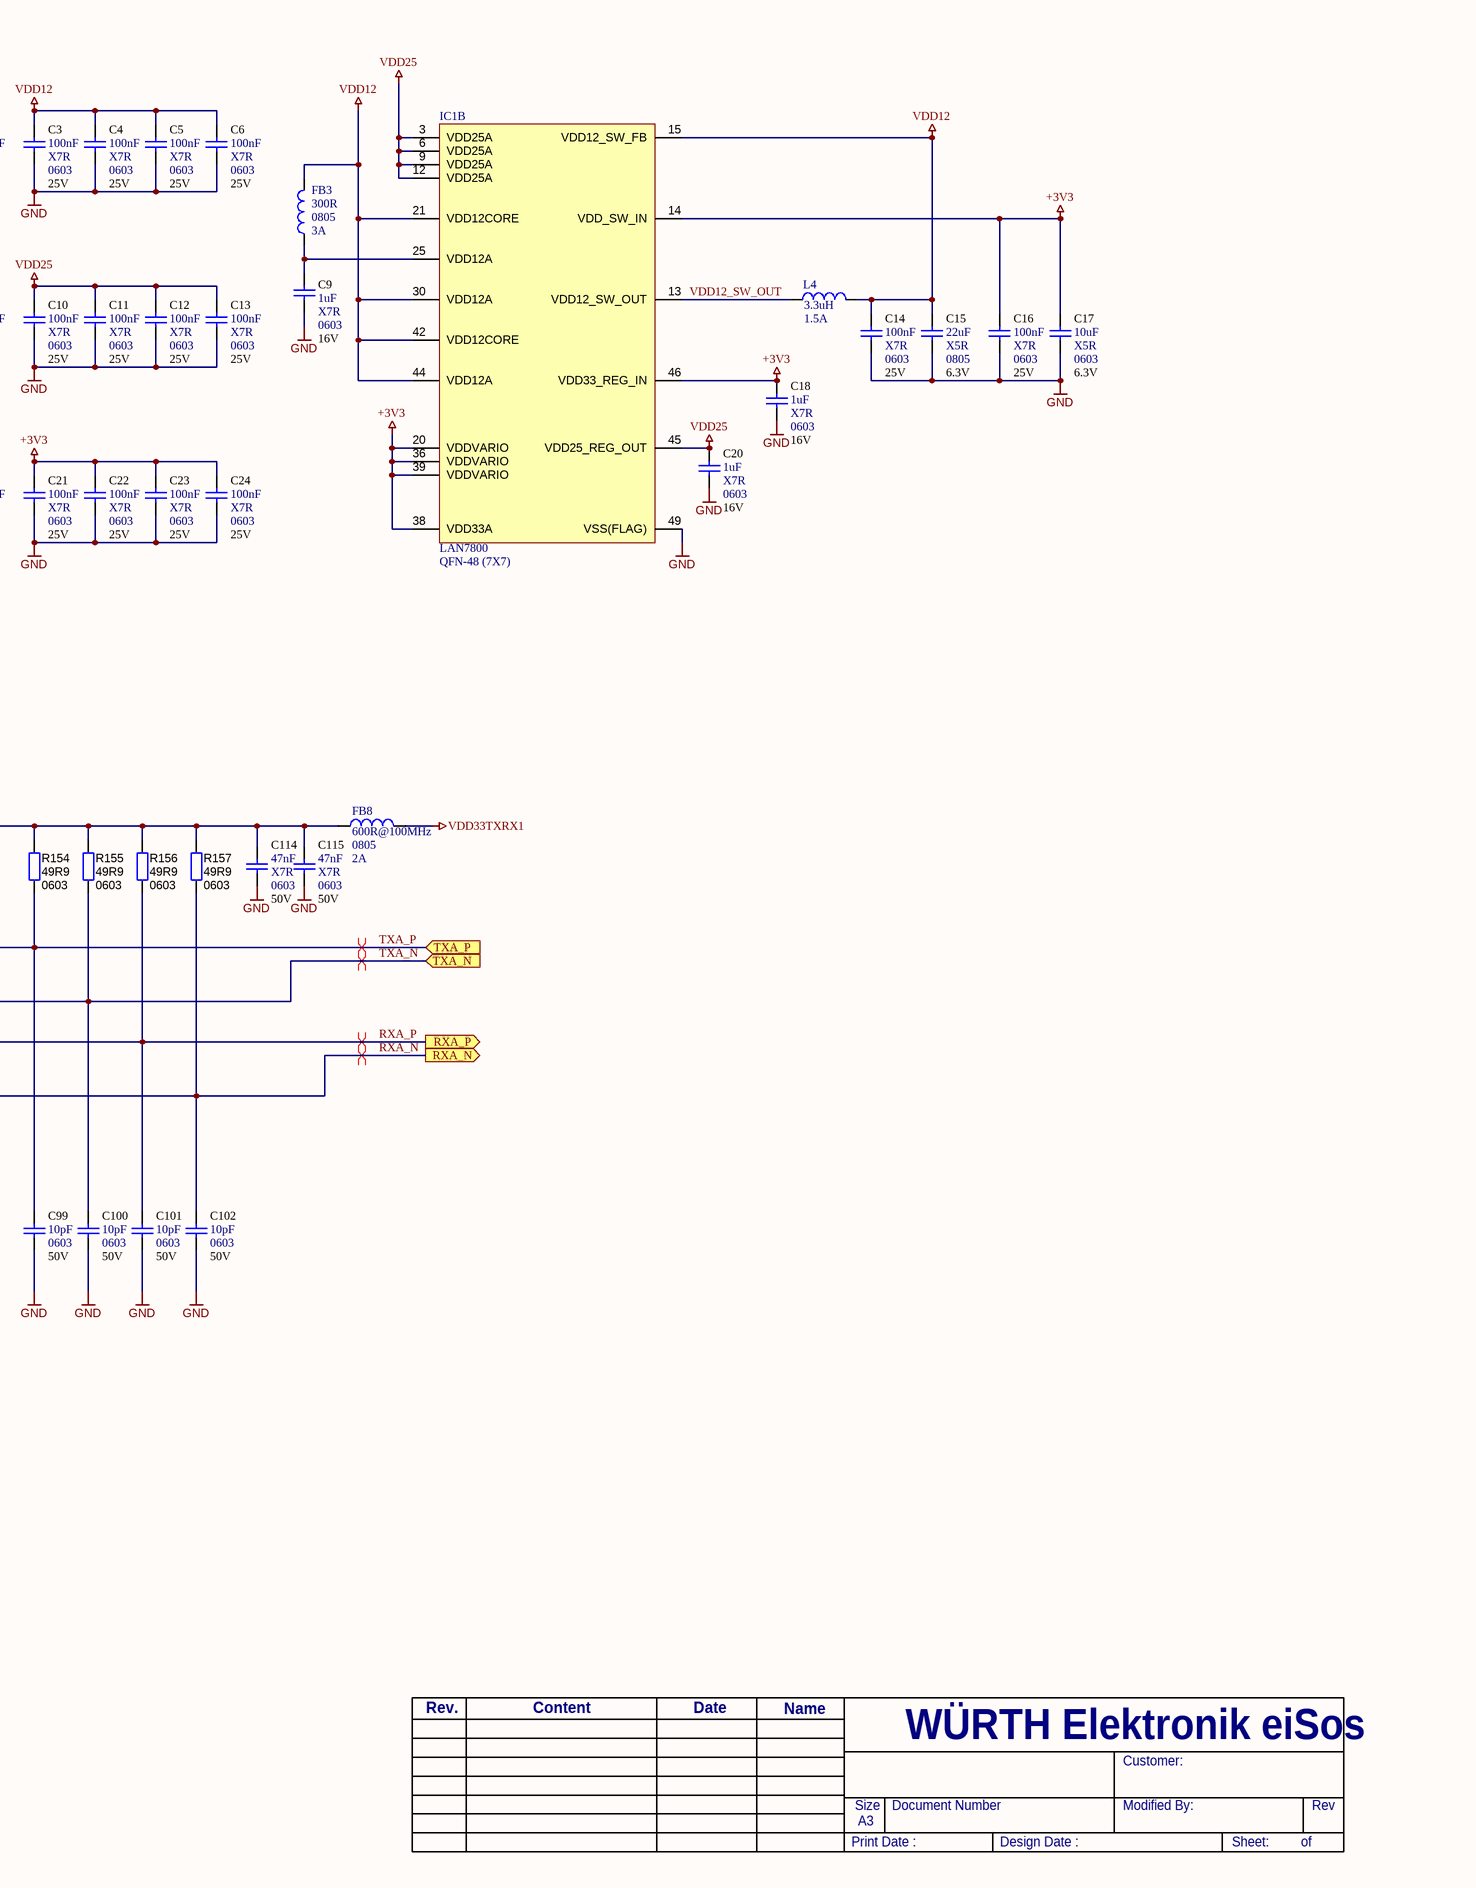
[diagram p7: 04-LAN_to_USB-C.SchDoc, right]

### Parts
C3  value 100nF  VDC_V: 25V  PackageReference: 0603  Dielectric: X7R  [CC1608-0603]  (hidden comment: 885012206071)
C4  value 100nF  VDC_V: 25V  PackageReference: 0603  Dielectric: X7R  [CC1608-0603]  (hidden comment: 885012206071)
C5  value 100nF  VDC_V: 25V  PackageReference: 0603  Dielectric: X7R  [CC1608-0603]  (hidden comment: 885012206071)
C6  value 100nF  VDC_V: 25V  PackageReference: 0603  Dielectric: X7R  [CC1608-0603]  (hidden comment: 885012206071)
C7  value 100nF  [CC1005-0402]  (hidden comment: 885012105018)
C8  value 100nF  [CC1005-0402]  (hidden comment: 885012105018)
C9  value 1uF  VDC_V: 16V  PackageReference: 0603  Dielectric: X7R  [CC1608-0603]  (hidden comment: 885012206052)
C10  value 100nF  VDC_V: 25V  PackageReference: 0603  Dielectric: X7R  [CC1608-0603]  (hidden comment: 885012206071)
C11  value 100nF  VDC_V: 25V  PackageReference: 0603  Dielectric: X7R  [CC1608-0603]  (hidden comment: 885012206071)
C12  value 100nF  VDC_V: 25V  PackageReference: 0603  Dielectric: X7R  [CC1608-0603]  (hidden comment: 885012206071)
C13  value 100nF  VDC_V: 25V  PackageReference: 0603  Dielectric: X7R  [CC1608-0603]  (hidden comment: 885012206071)
C14  value 100nF  VDC_V: 25V  PackageReference: 0603  Dielectric: X7R  [CC1608-0603]  (hidden comment: 885012206071)
C15  value 22uF  VDC_V: 6.3V  PackageReference: 0805  Dielectric: X5R  [CC2012-0805]  (hidden comment: 885012107005)
C16  value 100nF  VDC_V: 25V  PackageReference: 0603  Dielectric: X7R  [CC1608-0603]  (hidden comment: 885012206071)
C17  value 10uF  VDC_V: 6.3V  PackageReference: 0603  Dielectric: X5R  [CC1608-0603]  (hidden comment: 885012106006)
C18  value 1uF  VDC_V: 16V  PackageReference: 0603  Dielectric: X7R  [CC1608-0603]  (hidden comment: 885012206052)
C19  value 10nF  PackageReference: 1206  VDC_V: 100V  [CC3216-1206]  (hidden comment: 885012208112)
C20  value 1uF  VDC_V: 16V  PackageReference: 0603  Dielectric: X7R  [CC1608-0603]  (hidden comment: 885012206052)
C21  value 100nF  VDC_V: 25V  PackageReference: 0603  Dielectric: X7R  [CC1608-0603]  (hidden comment: 885012206071)
C22  value 100nF  VDC_V: 25V  PackageReference: 0603  Dielectric: X7R  [CC1608-0603]  (hidden comment: 885012206071)
C23  value 100nF  VDC_V: 25V  PackageReference: 0603  Dielectric: X7R  [CC1608-0603]  (hidden comment: 885012206071)
C24  value 100nF  VDC_V: 25V  PackageReference: 0603  Dielectric: X7R  [CC1608-0603]  (hidden comment: 885012206071)
C29  value 1uF  VDC_V: 16V  [CC1608-0603]  (hidden comment: 885012206052)
C30  value 15pF  [CC1005-0402]  (hidden comment: 885012005056)
C31  value 15pF  [CC1005-0402]  (hidden comment: 885012005056)
C40  value 100nF  VDC_V: 25V  PackageReference: 0603  Dielectric: X7R  [CC1608-0603]  (hidden comment: 885012206071)
C46  value 100nF  VDC_V: 25V  PackageReference: 0603  Dielectric: X7R  Populated: NP  [CC1608-0603]  (hidden comment: 885012206071)
C47  value 100nF  VDC_V: 25V  PackageReference: 0603  Dielectric: X7R  Populated: NP  [CC1608-0603]  (hidden comment: 885012206071)
C48  value 100nF  VDC_V: 25V  PackageReference: 0603  Dielectric: X7R  Populated: NP  [CC1608-0603]  (hidden comment: 885012206071)
C49  value 100nF  VDC_V: 25V  PackageReference: 0603  Dielectric: X7R  Populated: NP  [CC1608-0603]  (hidden comment: 885012206071)
C50  value 100nF  VDC_V: 25V  PackageReference: 0603  Dielectric: X7R  Populated: NP  [CC1608-0603]  (hidden comment: 885012206071)
C51  value 100nF  VDC_V: 25V  PackageReference: 0603  Dielectric: X7R  Populated: NP  [CC1608-0603]  (hidden comment: 885012206071)
C98  value 22nF  VDC_V: 50V  PackageReference: 0603  [CC1608-0603]  (hidden comment: 885012206091)
C99  value 10pF  VDC_V: 50V  PackageReference: 0603  [CC1608-0603]  (hidden comment: 885012006051)
C100  value 10pF  VDC_V: 50V  PackageReference: 0603  [CC1608-0603]  (hidden comment: 885012006051)
C101  value 10pF  VDC_V: 50V  PackageReference: 0603  [CC1608-0603]  (hidden comment: 885012006051)
C102  value 10pF  VDC_V: 50V  PackageReference: 0603  [CC1608-0603]  (hidden comment: 885012006051)
C103  value 1nF  VDC_V: 100V  PackageReference: 0805  Dielectric: X7R  [CC2012-0805]  (hidden comment: 885012207116)
C114  value 47nF  VDC_V: 50V  PackageReference: 0603  Dielectric: X7R  [CC1608-0603]  (hidden comment: 885012206093)
C115  value 47nF  VDC_V: 50V  PackageReference: 0603  Dielectric: X7R  [CC1608-0603]  (hidden comment: 885012206093)
C127  value 10nF  PackageReference: 1206  VDC_V: 100V  [CC3216-1206]  (hidden comment: 885012208112)
D2  Voltage: 3.3V  [DFN1210-6L 1.2X1.0]  (hidden comment: 824012823)
D3  Voltage: 3.3V  [DFN1210-6L 1.2X1.0]  (hidden comment: 824012823)
D4  Voltage: 3.3V  [DFN1210-6L 1.2X1.0]  (hidden comment: 824012823)
FB3  value 300R  PackageReference: 0805  I DC: 3A  [CF2012-0805]  (hidden comment: 742792031)
FB8  value 600R@100MHz  PackageReference: 0805  I DC: 2A  [CF2012-0805]  (hidden comment: 742792040)
IC1  value LAN7800  PackageReference: QFN-48 (7X7)  [QFN-48 7x7MM]  (hidden comment: LAN7800/Y9X)  (parts A,B of 2)
IC3  PackageReference: SO-8  [SO-8N]  (hidden comment: 93AA66C-I/SN)
L2  7442335600  [INDUCTOR_WE-CNSW-HF-0504]
L3  7442335600  [INDUCTOR_WE-CNSW-HF-0504]
L4  value 3.3uH  I DC: 1.5A  [Inductor_WE-LQS 3015]  (hidden comment: 74404032033)
L5  value 90R @ 100MHz  [INDUCTOR_WE-CNSW-1206]  (hidden comment: 744232090)
R2  value 5k1  PackageReference: 0603  [CR1608-0603]  (hidden comment: RC0603FR-075K1L)
R5  value 10k  PackageReference: 0603  [CR1608-0603]  (hidden comment: 560112116005)
R6  value 10k  PackageReference: 0603  [CR1608-0603]  (hidden comment: 560112116005)
R7  value 2k  PackageReference: 0603  [CR1608-0603]  (hidden comment: 560112116091)
R8  value 10k  PackageReference: 0603  Populated: NP  [CR1608-0603]  (hidden comment: RC0603FR-0710KL)
R11  value 12k  PackageReference: 0603  [CR1608-0603]  (hidden comment: 560112116040)
R12  value 10k  PackageReference: 0603  [CR1608-0603]  (hidden comment: 560112116005)
R17  value 10k  PackageReference: 0603  [CR1608-0603]  (hidden comment: 560112116005)
R18  value 10k  PackageReference: 0603  [CR1608-0603]  (hidden comment: 560112116005)
R153  value 0R  PackageReference: 0603  [CR1608-0603]  (hidden comment: RC0603FR-070RL)
R154  value 49R9  PackageReference: 0603  [CR1608-0603]  (hidden comment: 560112116133)
R155  value 49R9  PackageReference: 0603  [CR1608-0603]  (hidden comment: 560112116133)
R156  value 49R9  PackageReference: 0603  [CR1608-0603]  (hidden comment: 560112116133)
R157  value 49R9  PackageReference: 0603  [CR1608-0603]  (hidden comment: 560112116133)
R158  value 75R  PackageReference: 0805  [CR2012-0805]  (hidden comment: RC0805FR-0775RL)
R159  value 75R  PackageReference: 0805  [CR2012-0805]  (hidden comment: RC0805FR-0775RL)
R160  value 0R  PackageReference: 1206  [CR3216-1206]  (hidden comment: CRCW12060000Z0EA)
R161  value 0R  PackageReference: 1206  [CR3216-1206]  (hidden comment: CRCW12060000Z0EA)
R198  value 0R  PackageReference: 1206  [CR3216-1206]  (hidden comment: CRCW12060000Z0EA)
R199  value 0R  PackageReference: 1206  [CR3216-1206]  (hidden comment: CRCW12060000Z0EA)
TP1  (no value)  [TESTPOINT 1.5mm]
VAR2  PackageReference: 1206  [CV3216-1206]  (hidden comment: 82551600)
X1  value USB-C Receptacle  [632723300011_USB_TypeC]  (hidden comment: 632723300011)
X8  7490100110A  [7490100110A]
Y1  value 25MHz  [CRYSTAL_3225]  (hidden comment: 830055299)

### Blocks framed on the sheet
Option (skip magnetic): R160 R161 R198 R199

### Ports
RXA_N (out), RXA_P (out), TXA_N (in), TXA_P (in)

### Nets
+3V3: C16.1 C17.2 C18.1 C21.1 C22.1 C23.1 C24.1 C40.1 C50.1 C51.1 IC1.14(VDD_SW_IN) IC1.20(VDDVARIO) IC1.36(VDDVARIO) IC1.38(VDD33A) IC1.39(VDDVARIO) IC1.46(VDD33_REG_IN) IC3.8(VCC) R5.1 R6.1 R8.2
GND: C3.2 C4.2 C5.2 C6.2 C9.2 C10.2 C11.2 C12.2 C13.2 C14.2 C15.1 C16.2 C17.1 C18.2 C19.1 C20.2 C21.2 C22.2 C23.2 C24.2 C29.2 C30.1 C31.1 C40.2 C46.2 C47.2 C48.2 C49.2 C50.2 C51.2 C98.2 C99.2 C100.2 C101.2 C102.2 C103.2 C114.2 C115.2 C127.1 IC1.49(VSS(FLAG)) IC3.5(VSS) R2.2 R7.2 R11.2 R12.2 R17.2 R18.2 VAR2.2 X1.A1(GND) X1.A12(GND) X1.B1(GND) X1.B12(GND) X1.SH1 X1.SH2 X1.SH3 X1.SH4 Y1.2 Y1.4
SHIELD: C19.2 C127.2 D2.3(GND) D3.3(GND) D4.3(GND) VAR2.1
VDD12: C3.1 C4.1 C5.1 C6.1 C14.1 C15.2 C46.1 C47.1 FB3.2 IC1.15(VDD12_SW_FB) IC1.21(VDD12CORE) IC1.30(VDD12A) IC1.42(VDD12CORE) IC1.44(VDD12A) L4.2
VDD25: C10.1 C11.1 C12.1 C13.1 C20.1 C48.1 C49.1 IC1.3(VDD25A) IC1.6(VDD25A) IC1.9(VDD25A) IC1.12(VDD25A) IC1.45(VDD25_REG_OUT)
VDD33TXRX1: FB8.2
EECLK: IC1.19(EECLK/LED1/GPIO3) IC3.2(CLK)
EECS: IC1.16(EECS/GPIO0) IC3.1(CS) R18.1
EEDI: IC1.17(EEDI/GPIO1) IC3.4(DO)
EEDO: IC1.18(EEDO/LED0/GPIO2) IC3.3(DI)
LED2: IC1.24(SUSPEND_N/LED2/GPIO5)
LED3: IC1.33(LED3_GPIO6)
PME_MODE: IC1.43(PME_MODE/GPIO7) TP1.1
PME_N/CONNECT: IC1.22(PME_N/GPIO4) R8.1
RXA_N: C102.1 R157.1 R199.2 X8.9(D2-) ; port RXA_N
RXA_P: C101.1 R156.1 R198.2 X8.11(D2+) ; port RXA_P
TEST: IC1.34(TEST) R12.1
TR0_N: IC1.2(TR0N) R161.1 X8.3(X1-)
TR0_P: IC1.1(TR0P) R160.1 X8.1(X1+)
TR1_N: IC1.5(TR1N) R199.1 X8.8(X2-)
TR1_P: IC1.4(TR1P) R198.1 X8.6(X2+)
TXA_N: C100.1 R155.1 R161.2 X8.14(D1-) ; port TXA_N
TXA_P: C99.1 R154.1 R160.2 X8.16(D1+) ; port TXA_P
USB2D1_N: D4.2(IO2) D4.5(IO2) L5.4(Pri2) X1.A7(D-) X1.B7(D-)
USB2D1_P: D4.1(IO1) D4.6(IO1) L5.1(Pri1) X1.A6(D+) X1.B6(D+)
USB2D_N: IC1.27(USB2_DM) L5.3(Sec2)
USB2D_P: IC1.26(USB2_DP) L5.2(Sec1)
USB3RX1_N: D3.2(IO2) D3.5(IO2) L3.4(Pri2) X1.B11(SSRXp1)
USB3RX1_P: D3.1(IO1) D3.6(IO1) L3.1(Pri1) X1.B10(SSRXn1)
USB3RX_N: IC1.32(USB3_RXDM) L3.3(Sec2)
USB3RX_P: IC1.31(USB3_RXDP) L3.2(Sec1)
USB3TX1_N: D2.2(IO2) D2.5(IO2) L2.4(Pri2) X1.A3(SSTXn1)
USB3TX1_P: D2.1(IO1) D2.6(IO1) L2.1(Pri1) X1.A2(SSTXp1)
USB3TX_N: C7.2 IC1.29(USB3_TXDM)
USB3TX_P: C8.2 IC1.28(USB3_TXDP)
USBRBIAS: IC1.37(USBRBIAS) R11.1
VDD12_SW_OUT: IC1.13(VDD12_SW_OUT) L4.1
NetC7_1: C7.1 L2.3(Sec2)
NetC8_1: C8.1 L2.2(Sec1)
NetC9_1: C9.1 FB3.1 IC1.25(VDD12A)
NetC29_1: C29.1 IC1.48(REF_FILT)
NetC30_2: C30.2 IC1.40(XI) Y1.1
NetC31_2: C31.2 IC1.41(XO) Y1.3
NetC98_1: C98.1 R153.1 X8.10(CD2) X8.15(CD1)
NetC103_1: C103.1 R158.1 R159.1
NetC114_1: C114.1 C115.1 FB8.1 R153.2 R154.2 R155.2 R156.2 R157.2
NetIC1_23: IC1.23(VBUS_DET) R5.2
NetIC1_35: IC1.35(RESET_N/PME_CLEAR) R6.2
NetIC1_47: IC1.47(REF_REXT) R7.1
NetIC3_6: IC3.6(ORG) R17.1
NetR2_1: R2.1 X1.A5(CC1)
NetR158_2: R158.2 X8.2(CX1)
NetR159_2: R159.2 X8.7(CX2)

Not connected (* = marked no-connect by the designer): IC1 7(TR2P)* 8(TR2N)* 10(TR3P)* 11(TR3N)*; IC3 7(NC)*; X1 A4(VBUS)* A8(SBU1)* A9(VBUS)* A10(SSRXn2)* A11(SSRXp2)* B2(SSTXp2)* B3(SSTXn2)* B4(VBUS)* B5(CC2)* B8(SBU2)* B9(VBUS)*

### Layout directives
differential pair: RXA_N, RXA_P, TR0_N, TR0_P, TR1_N, TR1_P, TXA_N, TXA_P, USB2D1_N, USB2D1_P, USB2D_N, USB2D_P, USB3RX1_N, USB3RX1_P, USB3RX_N, USB3RX_P, USB3TX1_N, USB3TX1_P, USB3TX_N, USB3TX_P

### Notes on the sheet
- (near X1) USB TYPE-C Port
- Rev.
- Content
- Date
- Name
- WÜRTH Elektronik eiSos
- Customer:
- Print Date :
- Size
- A3
- Document Number
- Design Date :
- Modified By:
- Sheet:
- of
- Rev

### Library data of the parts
C3-C6 C10-C14 C16 C21-C24 C40 C46-C51 = 885012206071: as C66-C72 on sheet 03-LAN_3-Ports_Switch
C7 C8 = 885012105018: CAP, CERM, 100nF, 25V, +/-20%, X5R, 0402; Manufacturer: Wurth; Polarized: N; TaMax_C: 85; TaMin_C: -55; Tolerance_%: 20; CompType: Capacitor
C9 C18 C20 C29 = 885012206052: CAP, CERM, 1uF, 16V, +/-10%, X7R, 0603; Manufacturer: Wurth; Polarized: N; TaMax_C: 125; TaMin_C: -55; Tolerance_%: 10%; CompType: Capacitor
C15 = 885012107005: CAP, CERM, 22uF, 6.3V, +/-20%, X5R, 0805; Manufacturer: Wurth; Polarized: N; TaMax_C: 85; TaMin_C: -55; Tolerance_%: 20; CompType: Capacitor
C17 = 885012106006: CAP, CERM, 10uF, 6.3V, +/-20%, X5R, 0603; Manufacturer: Wurth; Polarized: N; TaMax_C: 85; TaMin_C: -55; Tolerance_%: 10; CompType: Capacitor
C19 C127 = 885012208112: CAP, CERM, 10nF, 100V, +/-10%, X7R, 1206; Manufacturer: Wurth; Polarized: N; TaMax_C: 125; TaMin_C: -55; Tolerance_%: 10; CompType: Capacitor
C30 C31 = 885012005056: as C82 on sheet 03-LAN_3-Ports_Switch
C98 = 885012206091: as C89 on sheet 03-LAN_3-Ports_Switch
C99-C102 = 885012006051: as C85 on sheet 03-LAN_3-Ports_Switch
C103 = 885012207116: CAP, CERM, 1nF, 100V, +/-10%, X7R, 0805; Manufacturer: Wurth; Polarized: N; TaMax_C: 125; TaMin_C: -55; Tolerance_%: 10; CompType: Capacitor
C114 C115 = 885012206093: as C112 on sheet 03-LAN_3-Ports_Switch
D2-D4 = 824012823: DIODE, TVS Super Speed , 3.3V, DFN1210-6L; Manufacturer: Wurth
FB3 = 742792031: as FB2 on sheet 03-LAN_3-Ports_Switch
FB8 = 742792040: Ferrite Bead 600R @ 100MHz / 0805 / 2.0A; Manufacturer: Wurth; R @ 100MHz: 1500R
IC1 = LAN7800/Y9X: IC USB3.1 to 1G Ethernet Bridge, 3.3V, QFN-48; Manufacturer: Microchip
IC3 = 93AA66C-I/SN: IC EEPROM, SPI, 4kb, 16MHz, 1.8-5.5V, SO-8; Manufacturer: Microchip
L2 L3 = 7442335600: Common Mode Chokes 60R @ 100MHz / 1x1.2mm / 600mA; Manufacturer: Wurth; I DC: 0.6A
L4 = 74404032033: Inductor 3.3uH / 3015 / 1.5A; Manufacturer: Wurth
L5 = 744232090: Common Mode Chokes 90R @ 100MHz / 1206 / 370mA; Manufacturer: Wurth; I DC: 0.37A
R2 = RC0603FR-075K1L: RES, 5.1kohm, 1%, 0.1W, 0603; Manufacturer: Yageo; CompType: Resistor; Power_W: 0.1
R5 R6 R12 R17 R18 = 560112116005: as R73 on sheet 03-LAN_3-Ports_Switch
R7 = 560112116091: as R74 on sheet 03-LAN_3-Ports_Switch
R8 = RC0603FR-0710KL: RES, 10kohm, 1%, 0.1W, 0603; Manufacturer: Yageo; CompType: Resistor; Power_W: 0.1
R11 = 560112116040: RES, 12kohm, 1%, 0.1W, 0603; Manufacturer: Wurth; CompType: Resistor; Power_W: 0.1
R153 = RC0603FR-070RL: as R81 on sheet 03-LAN_3-Ports_Switch
R154-R157 = 560112116133: as R77-R80 on sheet 03-LAN_3-Ports_Switch
R158 R159 = RC0805FR-0775RL: RES, 75 ohm, 1%, 0.125W, 0805; Manufacturer: Yageo; CompType: Resistor; Power_W: 0.125
R160 R161 R198 R199 = CRCW12060000Z0EA: RES, 0 ohm, -%, 0.25W, 1206; Manufacturer: Vishay; CompType: Resistor; Power_W: 0.25
TP1 = TP / 1.5mm: Test Point, SMT, Miniature; Value: 1.5mm
VAR2 = 82551600: Varistor, 85Vdc, 60Vac, 160pF, 1206; Manufacturer: Wurth
X1 = 632723300011: CON, USB, Type C, Female, 24P, Hor, SMT; Manufacturer: Wurth; CompType: Connector
X8 = 7490100110A: Trans, Ethernet, 10/100 Base-T, SMT; Manufacturer: Wurth; CompType: Transformer
Y1 = 830055299: as Y3 on sheet 03-LAN_3-Ports_Switch

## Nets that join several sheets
+3V3: 01-PSE_Power_MCU (17 pins), 02-10BASE-T1L_PHY (18 pins), 03-LAN_3-Ports_Switch (44 pins), 04-LAN_to_USB-C (20 pins)
GND: 01-PSE_Power_MCU (69 pins), 02-10BASE-T1L_PHY (17 pins), 03-LAN_3-Ports_Switch (66 pins), 04-LAN_to_USB-C (58 pins)
SHIELD: 01-PSE_Power_MCU (25 pins), 03-LAN_3-Ports_Switch (9 pins), 04-LAN_to_USB-C (6 pins)
VDD33TXRX1: 03-LAN_3-Ports_Switch (C79.1 FB6.2 IC13.74), 04-LAN_to_USB-C (FB8.2)
D_N: 01-PSE_Power_MCU (D17.1 D17.6 T1.4), 02-10BASE-T1L_PHY (R64.1 R65.1)
D_P: 01-PSE_Power_MCU (D17.2 D17.5 T1.1), 02-10BASE-T1L_PHY (R68.1 R69.1)
~{ETH_RST}: 01-PSE_Power_MCU (IC5.48), 03-LAN_3-Ports_Switch (R73.1 R75.1 S2.2 S2.4)
~{INT}: 01-PSE_Power_MCU (IC5.14), 02-10BASE-T1L_PHY (D7.2 IC9.25 R70.2 X6.3)
MDC: 01-PSE_Power_MCU (IC5.12), 02-10BASE-T1L_PHY (D6.2 IC9.27 X6.1)
MDIO: 01-PSE_Power_MCU (IC5.13), 02-10BASE-T1L_PHY (D8.2 IC9.26 R71.2 X6.2)
P0_INCLK: 02-10BASE-T1L_PHY (IC9.32 R55.1), 03-LAN_3-Ports_Switch (R121.1)
P0_IND0: 02-10BASE-T1L_PHY (IC9.31 R56.1), 03-LAN_3-Ports_Switch (R119.1)
P0_IND1: 02-10BASE-T1L_PHY (IC9.30 R57.1), 03-LAN_3-Ports_Switch (R118.1)
P0_IND2: 02-10BASE-T1L_PHY (IC9.29 R58.1), 03-LAN_3-Ports_Switch (R116.1)
P0_IND3: 02-10BASE-T1L_PHY (IC9.28 R59.1), 03-LAN_3-Ports_Switch (R114.1)
P0_INDV: 02-10BASE-T1L_PHY (IC9.33 R54.1), 03-LAN_3-Ports_Switch (IC13.37)
P0_INER: 02-10BASE-T1L_PHY (IC9.34 R53.1), 03-LAN_3-Ports_Switch (IC13.46)
P0_OUT/REF_CLK_MODE0: 02-10BASE-T1L_PHY (IC9.38), 03-LAN_3-Ports_Switch (R103.1 R124.1)
P0_OUTD0_MODE1: 02-10BASE-T1L_PHY (IC9.39), 03-LAN_3-Ports_Switch (R102.1 R126.1)
P0_OUTD1_MODE2: 02-10BASE-T1L_PHY (IC9.40), 03-LAN_3-Ports_Switch (R101.1 R128.1)
P0_OUTD2_MODE3: 02-10BASE-T1L_PHY (IC9.1), 03-LAN_3-Ports_Switch (R100.1 R130.1)
P0_OUTD3: 02-10BASE-T1L_PHY (IC9.2 R52.1), 03-LAN_3-Ports_Switch (R131.1)
P0_OUTDV: 02-10BASE-T1L_PHY (IC9.37), 03-LAN_3-Ports_Switch (IC13.34 R152.2 TP9.1)
P0_OUTER_SPEED: 02-10BASE-T1L_PHY (IC9.36), 03-LAN_3-Ports_Switch (IC13.28 R105.1)
~{RESET}: 02-10BASE-T1L_PHY (IC9.5), 03-LAN_3-Ports_Switch (IC10.2 IC13.12 R72.2 T4.3)
RXA_N: 03-LAN_3-Ports_Switch (IC13.77), 04-LAN_to_USB-C (C102.1 R157.1 R199.2 X8.9)
RXA_P: 03-LAN_3-Ports_Switch (IC13.78), 04-LAN_to_USB-C (C101.1 R156.1 R198.2 X8.11)
TXA_N: 03-LAN_3-Ports_Switch (IC13.75), 04-LAN_to_USB-C (C100.1 R155.1 R161.2 X8.14)
TXA_P: 03-LAN_3-Ports_Switch (IC13.76), 04-LAN_to_USB-C (C99.1 R154.1 R160.2 X8.16)

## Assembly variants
Prototype W Ideal Diode: not fitted C46 C47 C48 C49 C50 C51 C53 C54 C90 C91 C92 C93 C94 C95 C117 D19 R8 R20 R38 R41 R94 R95 R96 R97 R99 R110 R112 R113 R115 R117 R120 R129 R132 R133 R134 R135 R148 R149 R160 R161 R198 R199 T9 X6 X12 Y4
Prototype W/O Ideal Diode: not fitted C46 C47 C48 C49 C50 C51 C53 C54 C90 C91 C92 C93 C94 C95 C117 C121 C122 D19 IC6 R8 R20 R38 R43 R94 R95 R96 R97 R99 R110 R112 R113 R115 R117 R120 R129 R132 R133 R134 R135 R148 R149 R160 R161 R198 R199 T9 T11 X6 X12 Y4 Z1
